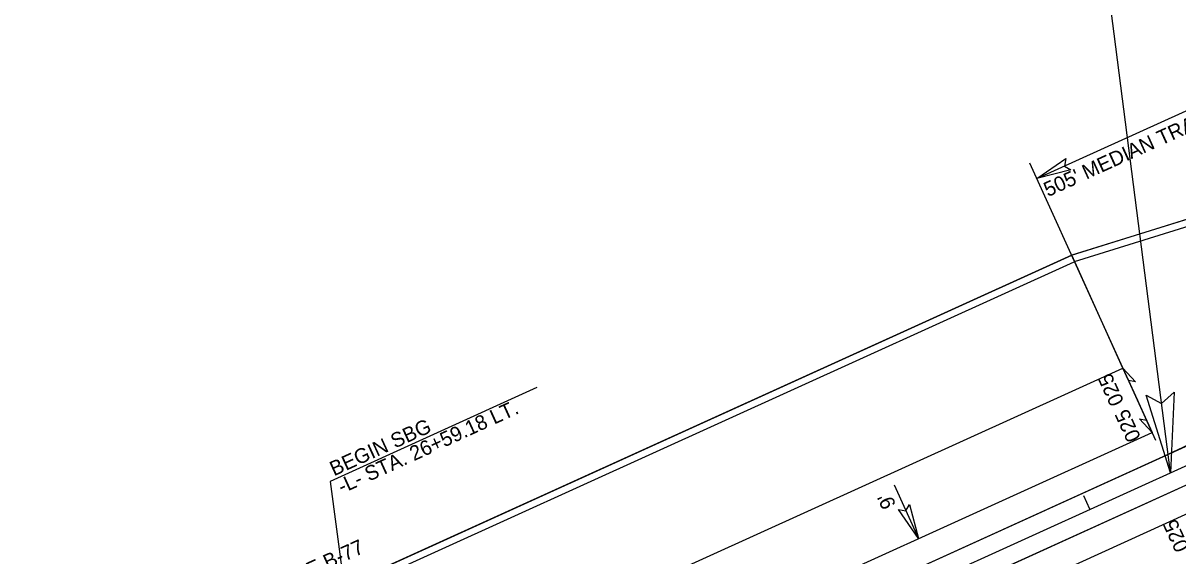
# Model space of a CAD drawing. Extents: x 2242984 to 2250974, y 661492 to 664681.
# Drawn here: x 2249051.2 to 2249442.6, y 663557.7 to 663738.5 of the extents above; entities that cross this region are included whole.
import ezdxf

# ---------------------------------------------------------------- set-up
doc = ezdxf.new("R2010")
doc.units = 0
for name, color, linetype in [('Prop Conc Shoulder Berm Gutter', 7, 'Continuous'), ('Prop Dimension', 7, 'Continuous'), ('Prop Dimension Text', 7, 'Continuous'), ('Prop DSN Text', 7, 'Continuous'), ('Prop EOT', 7, 'Continuous'), ('Prop Guardrail', 7, 'Continuous'), ('Prop Horizontal Alignment', 7, 'Continuous'), ('Prop Horizontal Alignment Tick Small', 7, 'Continuous'), ('Prop Paved Shoulder', 7, 'Continuous'), ('Prop Structure Anchor Unit CELL', 7, 'Continuous'), ('Prop Superelevation  Arrow CELL', 7, 'Continuous'), ('Prop Superelevation Label', 7, 'Continuous'), ('Prop Terminator CELL', 7, 'Continuous'), ('Scratch_Level_6', 7, 'Continuous'), ('Scratch_Level_8', 7, 'Continuous'), ('Typical Terminator CELL', 7, 'Continuous')]:
    doc.layers.add(name, color=color, linetype=linetype)

# ---------------------------------------------------------------- blocks, each defined once
blk = doc.blocks.new('TERMINATOR')
at = {"layer": 'Typical Terminator CELL'}
blk.add_lwpolyline([(-0.469, 0.081), (0, 0), (-0.471, -0.083), (-0.411, 0)], close=True, dxfattribs=at)

msp = doc.modelspace()

# ---------------------------------------------------------------- linework, layer by layer
at = {"layer": 'Prop Conc Shoulder Berm Gutter'}
for p in [(2249638.2, 663729.41), (2249160.98, 663545.56)]:
    msp.add_line(p, (2249407.42, 663657.51), dxfattribs=at)
at = {"layer": 'Prop Dimension'}
for p, q in [((2249394.77, 663685.73), (2249854.28, 663894.46)), ((2249440.09, 663585.95), (2249402.54, 663879.15)), ((2249435.11, 663596.91), (2249392.39, 663690.95)), ((2249346.39, 663581.84), (2249354.67, 663563.62))]:
    msp.add_line(p, q, dxfattribs=at)
at = {"layer": 'Prop DSN Text'}
for p, q in [((2249225.27, 663614.89), (2249155.21, 663582.96)), ((2249155.21, 663582.96), (2249160.01, 663547.69))]:
    msp.add_line(p, q, dxfattribs=at)
at = {"layer": 'Prop EOT'}
for p, q in [((2249423.96, 663621.46), (2249406.59, 663659.7)), ((2248850.37, 663360.9), (2249423.96, 663621.46)), ((2249423.96, 663621.46), (2249433.89, 663599.6)), ((2248200.21, 663039.2), (2249433.89, 663599.6)), ((2248212.61, 663011.89), (2249446.3, 663572.29))]:
    msp.add_line(p, q, dxfattribs=at)
at = {"layer": 'Prop Guardrail'}
for p, q in [((2249637.51, 663731.64), (2249406.59, 663659.7)), ((2249182.68, 663475.61), (2249637.91, 663682.4)), ((2249642.88, 663671.47), (2249233.17, 663485.36)), ((2249182.68, 663475.61), (2249592.39, 663661.72)), ((2249406.59, 663659.7), (2249154.1, 663545))]:
    msp.add_line(p, q, dxfattribs=at)
at = {"layer": 'Prop Horizontal Alignment'}
msp.add_line((2247500.8, 662705.02), (2249793.08, 663746.29), dxfattribs=at)
at = {"layer": 'Prop Horizontal Alignment Tick Small'}
msp.add_line((2249412.78, 663573.54), (2249410.71, 663578.09), dxfattribs=at)
at = {"layer": 'Prop Paved Shoulder'}
for p, q in [((2249437.63, 663591.42), (2249853.74, 663789.97)), ((2249655.6, 663737.28), (2249406.59, 663659.7)), ((2249160.01, 663547.69), (2249406.59, 663659.7)), ((2248894.79, 663344.83), (2249437.63, 663591.42)), ((2248895.78, 663332.1), (2249442.57, 663580.48))]:
    msp.add_line(p, q, dxfattribs=at)
at = {"layer": 'Prop Superelevation  Arrow CELL'}
for p in [(2249423.96, 663621.46), (2249433.89, 663599.6)]:
    msp.add_line(p, (2249428.92, 663610.53), dxfattribs=at)
for points in [[(2249423.96, 663621.46), (2249428.26, 663616.82), (2249425.87, 663617.24)], [(2249433.89, 663599.6), (2249429.59, 663604.24), (2249431.97, 663603.82)]]:
    msp.add_lwpolyline(points, close=True, dxfattribs=at)
at = {"layer": 'Prop Terminator CELL'}
msp.add_lwpolyline([(2249441.27, 663613.32), (2249440.09, 663585.95), (2249431.88, 663612.27), (2249437.08, 663609.46)], close=True, dxfattribs=at)
at = {"layer": 'Scratch_Level_6'}
for p, q in [((2249406.56, 663659.79), (2249637.47, 663731.73)), ((2249155.72, 663545.84), (2249406.56, 663659.79))]:
    msp.add_line(p, q, dxfattribs=at)
at = {"layer": 'Scratch_Level_8'}
for p, q in [((2249406.56, 663659.78), (2249637.48, 663731.73)), ((2249158.7, 663547.19), (2249406.56, 663659.78))]:
    msp.add_line(p, q, dxfattribs=at)

# ---------------------------------------------------------------- block references
at = {"layer": 'Prop Dimension'}
for p, xscale, yscale, rotation in [((2249394.77, 663685.73), 24.999999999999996, 24.999999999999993, -155.56987410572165), ((2249354.67, 663563.62), 25, 25, -65.56987410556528)]:
    msp.add_blockref('TERMINATOR', p, dxfattribs=dict(at, xscale=xscale, yscale=yscale, rotation=rotation))

# ---------------------------------------------------------------- texts
msp.add_text("9'", height=5, rotation=114.4301, dxfattribs=at).set_placement((2249347.15, 663575.03))
at = {"layer": 'Prop Dimension Text'}
msp.add_text("505' MEDIAN TRANSITION LT", height=5, rotation=24.4979, dxfattribs=at).set_placement((2249398.54, 663679.42))
at = {"layer": 'Prop DSN Text'}
for s, p in [('-L- STA. 26+59.18 LT.', (2249159.27, 663578.74)), ('BEGIN SBG', (2249156.55, 663584.71))]:
    msp.add_text(s, height=5, rotation=24.4979, dxfattribs=at).set_placement(p)
at = {"layer": 'Prop Structure Anchor Unit CELL'}
msp.add_text('TYPE B-77', height=5, rotation=24.4979, dxfattribs=at).set_placement((2249136.74, 663545.1))
at = {"layer": 'Prop Superelevation Label'}
for p in [(2249424.45, 663610.01), (2249430.15, 663597.84), (2249446.51, 663560.51)]:
    msp.add_text('025', height=5, rotation=114.4979, dxfattribs=at).set_placement(p)

doc.saveas('drawing.dxf')
